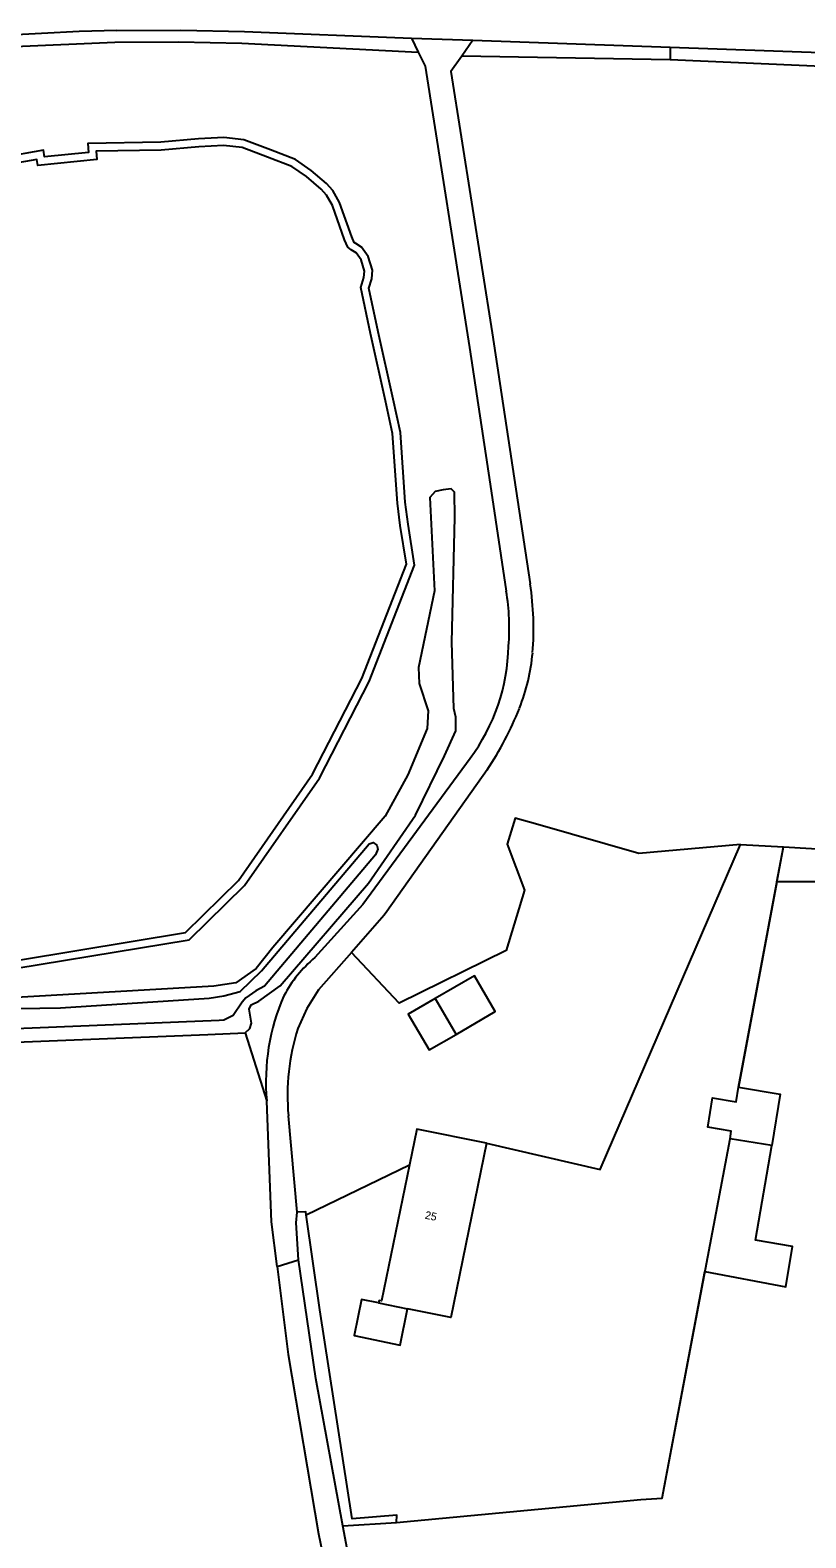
# Model space of a CAD drawing. Extents: x 140000 to 143000, y 403500 to 406000.
# Drawn here: x 140918.6 to 141017.3, y 405560.5 to 405752.3 of the extents above; entities that cross this region are included whole.
import ezdxf

# ---------------------------------------------------------------- set-up
doc = ezdxf.new("R2010")
doc.units = 0
for name, color, linetype in [('gg-afsc-erfafscheiding', 7, 'Continuous'), ('gg-afsc-hekwerk', 7, 'Continuous'), ('gg-anno-huisnummerreeks BGT', 7, 'Continuous'), ('gg-bbg-gedigitaliseerde bijgebouw', 7, 'Continuous'), ('gg-bbg-hoofdgebouw', 7, 'Continuous'), ('gg-bbg-luifel en loopbrug', 7, 'Continuous'), ('gg-bbg-overig bouwwerk', 7, 'Continuous'), ('gg-knt-bronhoudergrens', 7, 'Continuous'), ('gg-knt-onverhard', 7, 'Continuous'), ('gg-knt-verharding', 7, 'Continuous'), ('gg-kntw-bovenkant insteek waterloop', 7, 'Continuous'), ('gg-kntw-waterlijn', 7, 'Continuous'), ('gt-grn-groengrens', 7, 'Continuous'), ('gt-grn-weggrens', 7, 'Continuous'), ('gx-grn-maaiveld', 7, 'Continuous')]:
    doc.layers.add(name, color=color, linetype=linetype)

msp = doc.modelspace()

# ---------------------------------------------------------------- linework, layer by layer
at = {"layer": 'gg-afsc-erfafscheiding'}
for p, q in [((141000, 405748.58), (140973.52, 405749.05)), ((141008.96, 405648.76), (141014.4, 405648.44)), ((141013.57, 405644.01), (141014.4, 405648.44))]:
    msp.add_line(p, q, dxfattribs=at)
for points in [[(140903.95, 405749.17), (140916.68, 405750.25), (140929.42, 405750.83), (140937.49, 405750.86), (140945.57, 405750.7), (140967.99, 405749.55)], [(141212.81, 405714.74), (141196.1, 405719.35), (141151.33, 405731.99), (141132.83, 405736.89), (141121, 405739.43), (141109.08, 405741.62), (141099, 405743.09), (141088.85, 405744.13), (141078.61, 405745.02), (141068.35, 405745.65), (141020.26, 405747.68), (141000, 405748.58)], [(140976.64, 405610.74), (140991.13, 405607.4), (141008.96, 405648.76)]]:
    msp.add_lwpolyline(points, dxfattribs=at)
at = {"layer": 'gg-afsc-hekwerk'}
msp.add_line((141008.69, 405617.88), (141014.4, 405648.44), dxfattribs=at)
msp.add_lwpolyline([(140996.3, 405565.41), (140999, 405565.6), (141007.62, 405611.3)], dxfattribs=at)
at = {"layer": 'gg-bbg-gedigitaliseerde bijgebouw'}
msp.add_line((141012.94, 405610.44), (141007.62, 405611.3), dxfattribs=at)
for points in [[(141007.62, 405611.3), (141007.78, 405612.3), (141004.79, 405612.79), (141005.4, 405616.52), (141008.39, 405616.03), (141008.69, 405617.88)], [(141008.69, 405617.88), (141014.01, 405617.01), (141012.94, 405610.44)]]:
    msp.add_lwpolyline(points, dxfattribs=at)
at = {"layer": 'gg-bbg-hoofdgebouw'}
msp.add_line((140962.94, 405590.45), (140966.63, 405589.7), dxfattribs=at)
for points in [[(140976.64, 405610.74), (140967.8, 405612.55), (140966.87, 405607.99)], [(140976.64, 405610.74), (140972.11, 405588.58), (140966.63, 405589.7)], [(140966.87, 405607.99), (140963.33, 405590.68), (140963, 405590.75), (140962.94, 405590.45)]]:
    msp.add_lwpolyline(points, dxfattribs=at)
at = {"layer": 'gg-bbg-luifel en loopbrug'}
msp.add_line((140970.13, 405629.16), (140972.79, 405624.6), dxfattribs=at)
for points in [[(140972.79, 405624.6), (140977.77, 405627.51), (140975.12, 405632.06), (140970.13, 405629.16)], [(140970.13, 405629.16), (140966.72, 405627.17), (140969.38, 405622.61), (140972.79, 405624.6)], [(140962.94, 405590.45), (140960.78, 405590.89), (140959.84, 405586.27), (140965.69, 405585.07), (140966.63, 405589.7)]]:
    msp.add_lwpolyline(points, dxfattribs=at)
at = {"layer": 'gg-bbg-overig bouwwerk'}
msp.add_line((140958.41, 405562.06), (140965.2, 405562.5), dxfattribs=at)
for points in [[(140952.74, 405595.9), (140952.44, 405600.62), (140952.57, 405601.99)], [(140953.74, 405601.63), (140953.69, 405602.02), (140952.57, 405601.99)], [(140965.2, 405562.5), (140965.27, 405563.43), (140959.58, 405562.97), (140955.49, 405589.55), (140953.74, 405601.63)], [(140958.41, 405562.06), (140954.95, 405580.81), (140952.74, 405595.9)]]:
    msp.add_lwpolyline(points, dxfattribs=at)
at = {"layer": 'gg-knt-bronhoudergrens'}
for p, q in [((141013.57, 405644.01), (141008.69, 405617.88)), ((141018.94, 405644.01), (141013.57, 405644.01))]:
    msp.add_line(p, q, dxfattribs=at)
for points in [[(140965.2, 405562.5), (140996.3, 405565.41), (140999, 405565.6), (141004.44, 405594.43), (141014.7, 405592.5), (141015.58, 405597.6), (141010.87, 405598.41), (141012.94, 405610.44)], [(140950.03, 405595.06), (140951.44, 405583.89), (140955.31, 405561.08), (140960.97, 405533.63)], [(141008.91, 405398.62), (140980.09, 405475.53), (140963.63, 405534.08), (140958.41, 405562.06)]]:
    msp.add_lwpolyline(points, dxfattribs=at)
at = {"layer": 'gg-knt-onverhard'}
for p, q in [((140967.14, 405751.34), (140967.99, 405749.55)), ((140974.92, 405751.07), (140973.52, 405749.05)), ((140952.57, 405601.99), (140951.48, 405614.24)), ((140950.03, 405595.06), (140952.74, 405595.9))]:
    msp.add_line(p, q, dxfattribs=at)
for points in [[(140967.99, 405749.55), (140968.85, 405747.76), (140974.51, 405711.97), (140977.12, 405694.59), (140979.17, 405680.98)], [(140973.52, 405749.05), (140972.14, 405747.07), (140977.36, 405713.84), (140982.23, 405681.89)], [(140974.59, 405659.71), (140960.94, 405641.13), (140954.83, 405634.36)], [(140976.75, 405658.25), (140963.99, 405640.24), (140963.66, 405639.78), (140959.49, 405635.02)], [(140959.49, 405635.02), (140955.32, 405630.26), (140953.83, 405627.89), (140952.68, 405625.34)], [(140950.03, 405595.06), (140949.32, 405600.73), (140948.72, 405616.12)]]:
    msp.add_lwpolyline(points, dxfattribs=at)
for centre, radius, start, end in [((140951.24, 405676.29), 28.32, 355.3605, 9.5296), ((140942.81, 405676.16), 39.83, 355.6716, 8.2742), ((140954.48, 405674.55), 24.99, 323.5826, 358.7386), ((140958.07, 405675.25), 24.55, 338.0514, 355.1016), ((140940.29, 405682.3), 43.68, 326.5888, 338.1844), ((140965.29, 405621.9), 16.27, 129.997, 152.1714), ((140975.67, 405618.59), 27.06, 156.243, 185.2219), ((140979.94, 405616.78), 28.58, 162.5668, 185.0896)]:
    msp.add_arc(centre, radius, start, end, dxfattribs=at)
at = {"layer": 'gg-knt-verharding'}
for p, q in [((140974.92, 405751.07), (141000, 405750.19)), ((140945.98, 405624.81), (140948.72, 405616.12))]:
    msp.add_line(p, q, dxfattribs=at)
for points in [[(140929.66, 405752.31), (140937.78, 405752.34), (140945.89, 405752.18), (140967.14, 405751.34)], [(141000, 405750.19), (141020.33, 405749.48), (141068.44, 405747.45), (141078.74, 405746.81), (141089.02, 405745.92)], [(141014.4, 405648.44), (141026.54, 405647.74), (141073.04, 405651.15), (141098.24, 405651.14), (141117.55, 405652.09), (141144.3, 405659.3), (141152.5, 405661.81), (141155.83, 405662.06)]]:
    msp.add_lwpolyline(points, dxfattribs=at)
msp.add_arc((140938, 405427.39), 325.03, 91.4688, 95.9819, dxfattribs=at)
at = {"layer": 'gg-kntw-bovenkant insteek waterloop'}
for points in [[(140945.88, 405643.52), (140955.41, 405657.19), (140961.73, 405669.47), (140967.51, 405684.3), (140966.68, 405689.49), (140966.33, 405692.28), (140965.71, 405701.16), (140964.81, 405705.41), (140962.87, 405713.96), (140961.71, 405719.54), (140962.06, 405720.71), (140962.15, 405721.8), (140961.63, 405723.56), (140960.77, 405724.75), (140960.03, 405725.2), (140959.85, 405725.35), (140959.55, 405726.05), (140957.98, 405730.43), (140957.13, 405731.95), (140956.32, 405732.82), (140954.37, 405734.51), (140952.39, 405735.88), (140949.18, 405737.13), (140945.81, 405738.38), (140943.25, 405738.69), (140940.03, 405738.5), (140935.25, 405738.08), (140925.98, 405737.94), (140926.06, 405736.79), (140920.45, 405736.23), (140920.32, 405737.08), (140915.13, 405736.13)], [(140910.48, 405631.94), (140938.86, 405636.61), (140945.88, 405643.52)]]:
    msp.add_lwpolyline(points, dxfattribs=at)
at = {"layer": 'gg-kntw-waterlijn'}
for points in [[(140965.33, 405692.18), (140964.71, 405701.02), (140963.83, 405705.19), (140961.9, 405713.74), (140960.68, 405719.59), (140961.07, 405720.9), (140961.14, 405721.7), (140960.72, 405723.11), (140960.08, 405724), (140959.45, 405724.38), (140959.02, 405724.74), (140958.62, 405725.69), (140957.06, 405730.02), (140956.31, 405731.36), (140955.63, 405732.1), (140953.76, 405733.71), (140951.92, 405734.99), (140948.82, 405736.19), (140945.58, 405737.4), (140943.22, 405737.69), (140940.1, 405737.51), (140935.3, 405737.08), (140927.05, 405736.96), (140927.13, 405735.89), (140919.61, 405735.14), (140919.49, 405735.91), (140916.35, 405735.33)], [(140910.47, 405632.95), (140938.38, 405637.54), (140945.11, 405644.17), (140954.55, 405657.71), (140960.82, 405669.88), (140966.48, 405684.41), (140965.69, 405689.35), (140965.33, 405692.18)]]:
    msp.add_lwpolyline(points, dxfattribs=at)
at = {"layer": 'gt-grn-groengrens'}
for points in [[(140945.98, 405624.81), (140946.55, 405625.36), (140946.78, 405626.03), (140946.5, 405627.8), (140946.74, 405628.36), (140947.71, 405628.83), (140950.44, 405630.79), (140961.64, 405643.82), (140967.64, 405652.48), (140971.32, 405660.02), (140972.76, 405663.21), (140972.74, 405664.93), (140972.5, 405666.06), (140972.25, 405674.51), (140972.64, 405690.36), (140972.6, 405693.55), (140972.16, 405694.01), (140971.15, 405693.87), (140970.15, 405693.64), (140969.47, 405692.9), (140970.03, 405681.04), (140968.01, 405671.27), (140968.12, 405669.22), (140969.23, 405665.76), (140969.13, 405663.51), (140966.64, 405657.6), (140963.78, 405652.34), (140949.49, 405635.63), (140947.38, 405632.98), (140944.8, 405631.14), (140941.99, 405630.73), (140916.12, 405629.24)], [(141008.96, 405648.76), (140996.01, 405647.59), (140983.17, 405651.29), (140980.3, 405652.12), (140979.28, 405648.8), (140981.51, 405642.92), (140979.15, 405635.26), (140965.55, 405628.55), (140959.49, 405635.02)], [(140893.57, 405627.5), (140922.49, 405627.98), (140941.4, 405629.2), (140943.26, 405629.49), (140945.33, 405630.03), (140948.04, 405632.68), (140961.76, 405648.82), (140962.23, 405648.99), (140962.71, 405648.68), (140962.86, 405648.15), (140962.55, 405647.45), (140948.45, 405630.74), (140947.32, 405630.12), (140946.05, 405629.25), (140945.59, 405628.7), (140944.43, 405627.01), (140943.28, 405626.4), (140942.66, 405626.35), (140911.61, 405625.1)], [(140855.65, 405618.83), (140877.6, 405621.82), (140909.32, 405623.31), (140941.25, 405624.57), (140945.98, 405624.81)]]:
    msp.add_lwpolyline(points, dxfattribs=at)
at = {"layer": 'gt-grn-weggrens'}
for p, q in [((140967.14, 405751.34), (140974.92, 405751.07)), ((141000, 405750.19), (141000, 405748.58))]:
    msp.add_line(p, q, dxfattribs=at)
at = {"layer": 'gx-grn-maaiveld'}
msp.add_line((140953.74, 405601.63), (140966.87, 405607.99), dxfattribs=at)

# ---------------------------------------------------------------- texts
at = {"layer": 'gg-anno-huisnummerreeks BGT'}
msp.add_text('25', height=1, rotation=348.5, dxfattribs=at).set_placement((140968.77, 405601.16))

doc.saveas('drawing.dxf')
